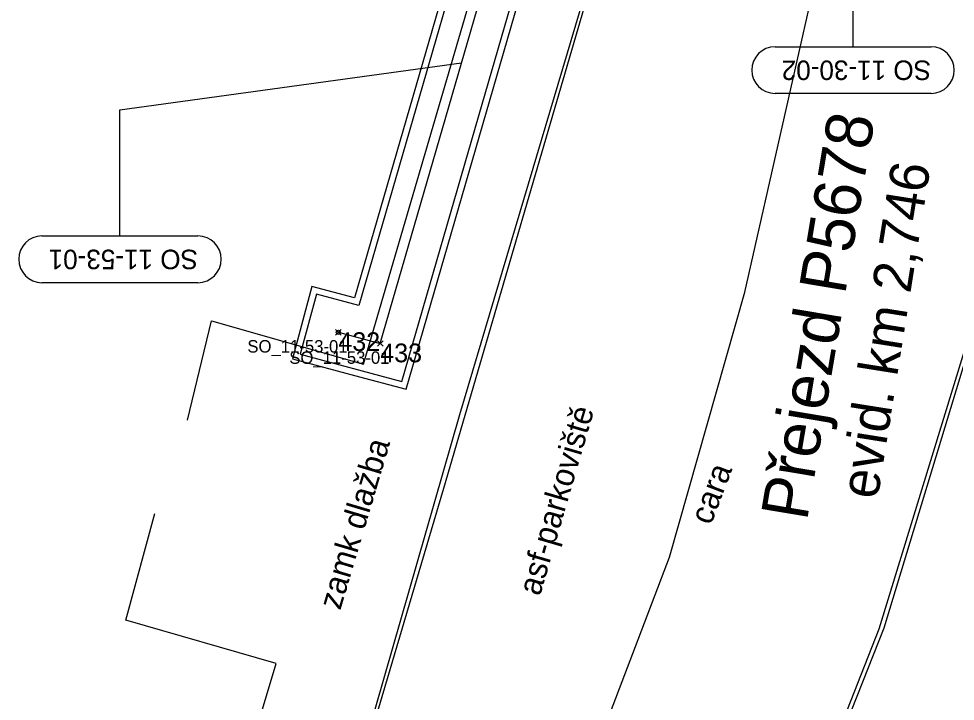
# Model space of a CAD drawing. Extents: x -728800 to -728100, y -1073200 to -1072700.
# Drawn here: x -728538.98 to -728508.97, y -1073092.03 to -1073070.14 of the extents above; entities that cross this region are included whole.
import ezdxf

# ---------------------------------------------------------------- set-up
doc = ezdxf.new("R2010")
doc.units = 0
for name, color, linetype in [('A2_OBVOD STAVBY', 7, 'Continuous'), ('B1_body_poloha', 7, 'Continuous'), ('B2_body_číslo', 7, 'Continuous'), ('B3_body_popiska', 7, 'Continuous'), ('B6_JŽM', 7, 'Continuous'), ('KOS_kabelová trasa VO', 7, 'Continuous'), ('KOS_nové prvky VO', 7, 'Continuous'), ('KTA_členění PS a SO', 7, 'Continuous'), ('ZA_02_Dočasný_do_1_roku', 7, 'Continuous')]:
    doc.layers.add(name, color=color, linetype=linetype)

msp = doc.modelspace()

# ---------------------------------------------------------------- linework, layer by layer
at = {"layer": 'A2_OBVOD STAVBY'}
msp.add_lwpolyline([(-728524.386, -1073065.843), (-728528.221, -1073079.089), (-728529.585, -1073078.721), (-728530.21, -1073081.039), (-728528.058, -1073081.619), (-728526.571, -1073082.019), (-728521.417, -1073064.22)], dxfattribs=at)
at = {"layer": 'B1_body_poloha'}
for p, q in [((-728528.827, -1073080.104), (-728528.65, -1073080.281)), ((-728528.827, -1073080.281), (-728528.65, -1073080.104)), ((-728527.484, -1073080.466), (-728527.308, -1073080.642)), ((-728527.484, -1073080.642), (-728527.308, -1073080.466))]:
    msp.add_line(p, q, dxfattribs=at)
at = {"layer": 'B2_body_číslo'}
for p, q in [((-728528.739, -1073080.192), (-728528.739, -1073080.192)), ((-728527.396, -1073080.554), (-728527.396, -1073080.554))]:
    msp.add_line(p, q, dxfattribs=at)
at = {"layer": 'B6_JŽM'}
for points in [[(-728533.573, -1073083.015), (-728532.804, -1073079.821), (-728527.933, -1073081.215), (-728522.9, -1073064.007)], [(-728531.131, -1073104.759), (-728528.363, -1073095.064), (-728524.847, -1073082.829), (-728520.445, -1073068.019), (-728519.555, -1073066.763), (-728518.532, -1073066.599), (-728513.679, -1073067.545)], [(-728513.171, -1073067.654), (-728514.129, -1073069.149), (-728515.701, -1073069.511), (-728520.385, -1073068.108), (-728525.367, -1073085.199), (-728528.271, -1073095.025), (-728524.268, -1073096.199), (-728523.716, -1073096.605), (-728523.622, -1073097.442)], [(-728524.69, -1073104.648), (-728518.127, -1073087.402), (-728515.708, -1073078.91), (-728513.171, -1073067.654)], [(-728518.577, -1073107.972), (-728511.413, -1073089.698), (-728508.676, -1073080.788), (-728506.273, -1073069.065)], [(-728518.469, -1073107.966), (-728511.248, -1073089.672), (-728508.568, -1073080.832), (-728506.346, -1073070.488)], [(-728534.577, -1073103.667), (-728530.73, -1073090.819), (-728535.551, -1073089.428), (-728534.621, -1073085.999)]]:
    msp.add_lwpolyline(points, dxfattribs=at)
at = {"layer": 'KOS_kabelová trasa VO'}
msp.add_lwpolyline([(-728528.739, -1073080.192), (-728527.396, -1073080.554), (-728522.184, -1073062.556), (-728521.71, -1073061.375), (-728517.306, -1073062.171), (-728515.639, -1073053.015), (-728515.016, -1073053.113), (-728515.09, -1073053.601)], dxfattribs=at)
at = {"layer": 'KOS_nové prvky VO'}
msp.add_circle((-728528.739, -1073080.192), 0.0665, dxfattribs=at)
at = {"layer": 'KTA_členění PS a SO'}
for p, q in [((-728512.245, -1073071.034), (-728512.245, -1073068.65)), ((-728535.738, -1073073.063), (-728524.792, -1073071.553)), ((-728535.738, -1073077.101), (-728535.738, -1073073.063))]:
    msp.add_line(p, q, dxfattribs=at)
for points in [[(-728514.745, -1073071.034), (-728509.745, -1073071.034)], [(-728509.745, -1073072.534), (-728514.745, -1073072.534)], [(-728538.238, -1073077.101), (-728533.238, -1073077.101)], [(-728533.238, -1073078.601), (-728538.238, -1073078.601)]]:
    msp.add_lwpolyline(points, dxfattribs=at)
for centre, start, end in [((-728514.739, -1073071.784), 90.4529, 269.5471), ((-728509.751, -1073071.784), 270.4529, 89.5471), ((-728538.232, -1073077.851), 90.4529, 269.5471), ((-728533.244, -1073077.851), 270.4529, 89.5471)]:
    msp.add_arc(centre, 0.75, start, end, dxfattribs=at)
at = {"layer": 'ZA_02_Dočasný_do_1_roku'}
msp.add_lwpolyline([(-728520.113, -1073054.153), (-728521.586, -1073059.338), (-728523.592, -1073059.251), (-728524.356, -1073059.629), (-728525.069, -1073060.25), (-728525.794, -1073061.679), (-728524.89, -1073061.94), (-728523.424, -1073063.243), (-728526.138, -1073072.616), (-728528.083, -1073079.333), (-728529.444, -1073078.966), (-728529.965, -1073080.897), (-728526.708, -1073081.775), (-728524.133, -1073072.881), (-728521.558, -1073063.987), (-728517.274, -1073064.874), (-728516.886, -1073063.083), (-728515.201, -1073062.537), (-728513.898, -1073062.774), (-728513.549, -1073060.856), (-728516.346, -1073060.346), (-728515.203, -1073056.818), (-728511.189, -1073055.123)], dxfattribs=at)

# ---------------------------------------------------------------- texts
at = {"layer": 'B2_body_číslo'}
for s, p in [('432', (-728528.739, -1073080.792)), ('433', (-728527.396, -1073081.154))]:
    msp.add_text(s, height=0.6, dxfattribs=at).set_placement(p)
at = {"layer": 'B3_body_popiska'}
for p in [(-728531.655, -1073080.842), (-728530.312, -1073081.204)]:
    msp.add_text('SO_11-53-01', height=0.4, dxfattribs=at).set_placement(p)
at = {"layer": 'B6_JŽM'}
for s, height, rotation, p in [('Přejezd P5678', 1.5, 80.4567, (-728513.723, -1073086.269)), ('evid. km 2,746', 1.25, 80.9732, (-728511.462, -1073085.577)), ('asf-parkoviště', 0.75, 73.7487, (-728522.281, -1073088.676)), ('zamk dlažba', 0.75, 73.4464, (-728528.679, -1073089.127)), ('cara', 0.75, 69.1656, (-728516.802, -1073086.402))]:
    msp.add_text(s, height=height, rotation=rotation, dxfattribs=at).set_placement(p)
at = {"layer": 'KTA_členění PS a SO'}
for s, p in [('SO 11-30-02', (-728509.746, -1073071.476)), ('SO 11-53-01', (-728533.239, -1073077.543))]:
    msp.add_text(s, height=0.625, rotation=180, dxfattribs=at).set_placement(p)

doc.saveas('drawing.dxf')
